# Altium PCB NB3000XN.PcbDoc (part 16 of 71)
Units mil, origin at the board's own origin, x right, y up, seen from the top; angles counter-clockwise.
Board outline 9527.56 x 6929.77 mil, 6 copper layers (Top Layer, GND+SHIELD, MidLayer1, MidLayer2, P2 - 3V3+5V0, Bottom Layer), stack 62.375 mil thick; 832 components, 1027 nets, 4655 pads, 4981 vias.
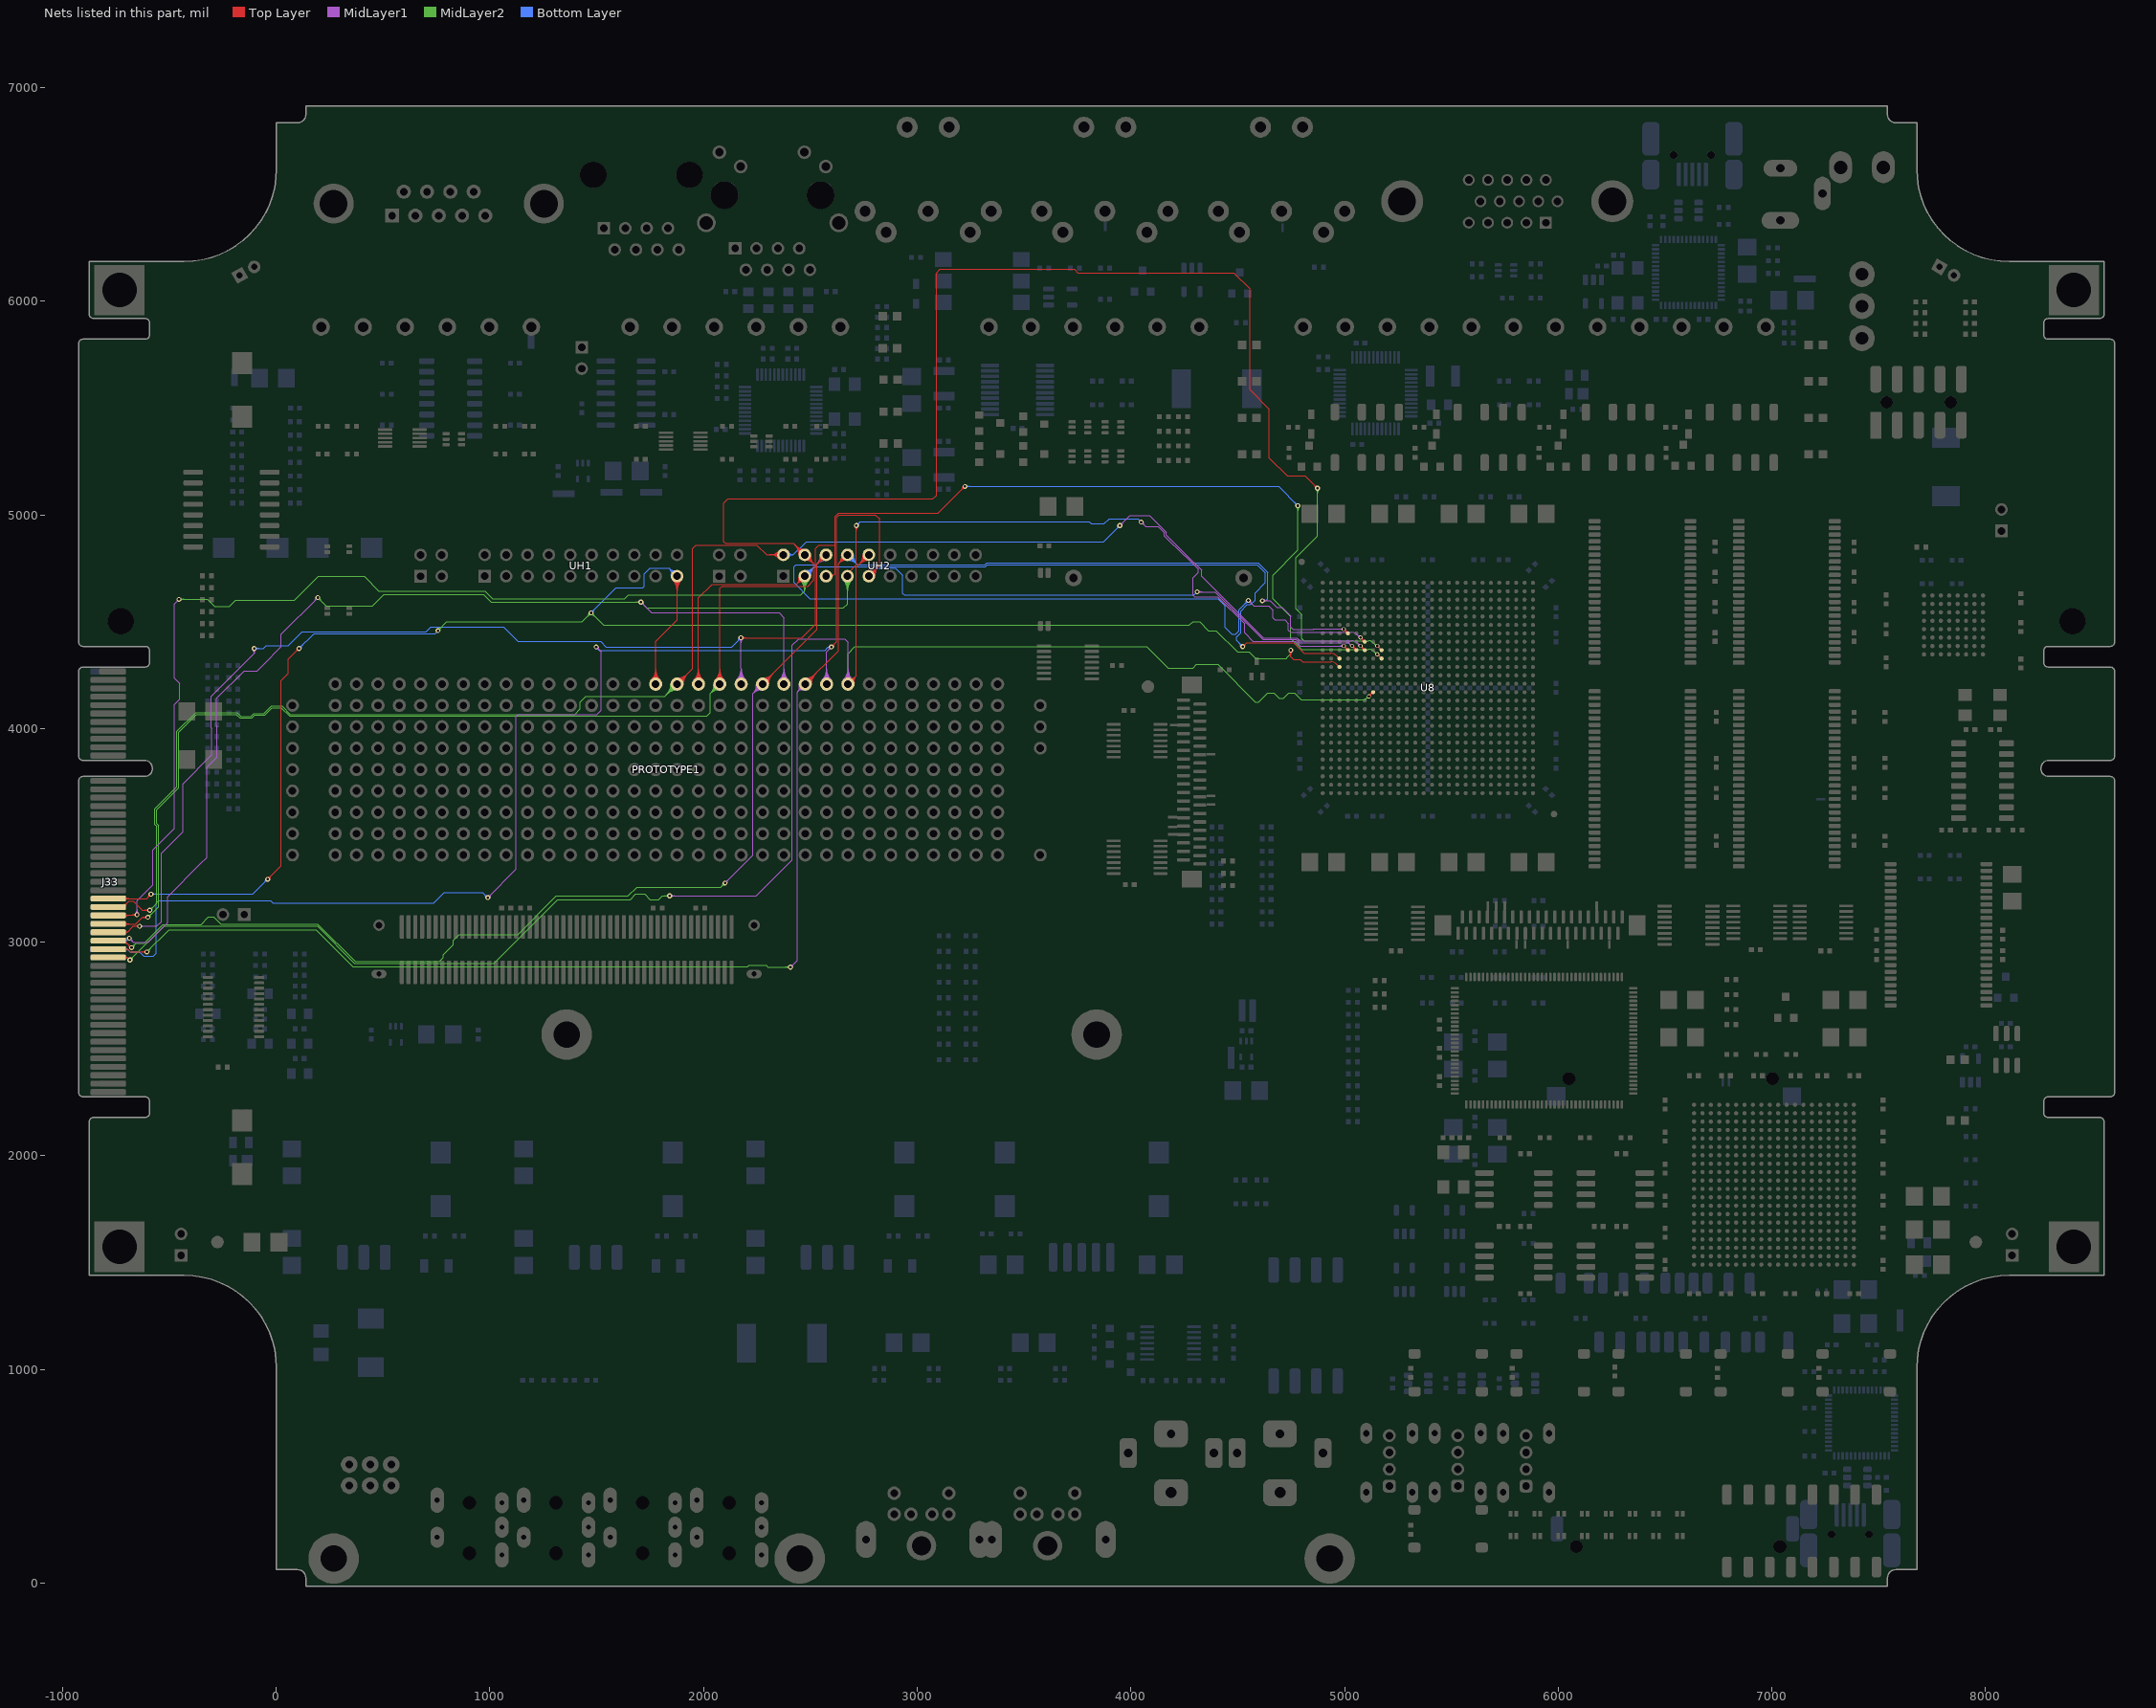
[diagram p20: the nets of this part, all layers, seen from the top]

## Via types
v1: diameter 23, hole 11.81, Top Layer to Bottom Layer, 3672 vias
v2: diameter 26, hole 11.81, Top Layer to Bottom Layer, 461 vias
v3: diameter 19, hole 11.81, Top Layer to Bottom Layer, tented both sides, 396 vias
v4: diameter 23.62, hole 11.81, Top Layer to Bottom Layer, 288 vias
v5: diameter 20, hole 11.81, Top Layer to Bottom Layer, 91 vias
v6: diameter 23, hole 11.81, Top Layer to Bottom Layer, tented both sides, 50 vias
v7: diameter 31, hole 11.81, Top Layer to Bottom Layer, 15 vias
v8: diameter 27.56, hole 11.81, Top Layer to Bottom Layer, tented both sides, 4 vias
v9: diameter 29, hole 11.81, Top Layer to Bottom Layer, 3 vias
v10: diameter 21, hole 11.81, Top Layer to Bottom Layer, 1 vias

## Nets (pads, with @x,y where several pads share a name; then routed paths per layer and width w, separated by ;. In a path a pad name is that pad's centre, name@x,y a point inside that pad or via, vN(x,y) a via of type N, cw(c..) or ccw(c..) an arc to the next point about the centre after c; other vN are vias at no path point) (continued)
ATE.UIO.IO17: J33.A26 PROTOTYPE1.H16 U8.L3 UH1.19 | length 9788.4
  Top Layer w4: J33.A26@-785.98,3204.04 -607.48,3204.04 v1(-586.48,3225.04) ; J33.A26@-711.58,3198.54 cw(c-698.3,3185.26) -698.3,3204.04 cw(c-698.3,3222.82) J33.A26@-711.58,3209.54 ; J33.A26@-708.76,3195.71 cw(c-688.65,3175.6) -688.65,3204.04 cw(c-688.65,3232.48) J33.A26@-708.76,3212.37 ; v1@-595.98,3225.04 cw(c-618.91,3225.04) -602.69,3208.82 cw(c-586.48,3192.61) v1@-586.48,3215.54 ; v1@-591.98,3225.04 cw(c-605.25,3225.04) -595.87,3215.65 cw(c-586.48,3206.26) v1@-586.48,3219.54 ; v1(-40,3295) 23.52,3358.52 23.52,4225.04 ; v1@-40,3300.5 ccw(c-40,3313.78) -30.61,3304.39 ccw(c-21.22,3295) v1@-34.5,3295 ; v1@-40,3304.5 ccw(c-40,3327.43) -23.78,3311.22 ccw(c-7.57,3295) v1@-30.5,3295 ; 43.96,4245.48 23.52,4225.04 ; v1@97.36,4375.04 cw(c74.42,4375.04) 90.64,4358.82 cw(c106.86,4342.61) v1@106.86,4365.54 ; v1@101.36,4375.04 cw(c88.08,4375.04) 97.47,4365.65 cw(c106.86,4356.26) v1@106.86,4369.54 ; v1(106.86,4375.04) 56.86,4325.04 56.86,4258.37 23.52,4225.04 ; PROTOTYPE1.H16@1755.62,4228.74 ccw(c1706.11,4278.25) 1776.12,4278.25 ccw(c1846.13,4278.25) PROTOTYPE1.H16@1796.63,4228.74 ; PROTOTYPE1.H16@1758.44,4225.91 ccw(c1715.77,4268.59) 1776.12,4268.59 ccw(c1836.48,4268.59) PROTOTYPE1.H16@1793.8,4225.91 ; PROTOTYPE1.H16@1761.27,4223.08 ccw(c1725.42,4258.93) 1776.12,4258.93 ccw(c1826.82,4258.93) PROTOTYPE1.H16@1790.97,4223.08 ; PROTOTYPE1.H16@1764.1,4220.26 ccw(c1735.08,4249.28) 1776.12,4249.28 ccw(c1817.16,4249.28) PROTOTYPE1.H16@1788.14,4220.26 ; PROTOTYPE1.H16@1766.93,4217.43 ccw(c1744.74,4239.62) 1776.12,4239.62 ccw(c1807.51,4239.62) PROTOTYPE1.H16@1785.31,4217.43 ; PROTOTYPE1.H16@1776.12,4208.23 1776.12,4408.37 1876.12,4508.37 UH1.19@1876.12,4713.23 ; UH1.19@1856.66,4693.77 cw(c1809.66,4646.78) 1876.12,4646.78 cw(c1942.58,4646.78) UH1.19@1895.59,4693.77 ; UH1.19@1859.48,4696.6 cw(c1819.32,4656.43) 1876.12,4656.43 cw(c1932.92,4656.43) UH1.19@1892.76,4696.6 ; UH1.19@1862.31,4699.43 cw(c1828.98,4666.09) 1876.12,4666.09 cw(c1923.26,4666.09) UH1.19@1889.93,4699.43 ; UH1.19@1865.14,4702.26 cw(c1838.63,4675.75) 1876.12,4675.75 cw(c1913.61,4675.75) UH1.19@1887.1,4702.26 ; v1@4741.81,4359.99 cw(c4725.59,4343.77) 4748.52,4343.77 cw(c4771.46,4343.77) v1@4755.24,4359.99 ; v1@4744.64,4362.82 cw(c4735.25,4353.43) 4748.52,4353.43 cw(c4761.8,4353.43) v1@4752.41,4362.82 ; v1@4755,4366.71 v1(4748.52,4366.71) 4748.52,4336.48 4761.6,4323.4 4792.92,4323.4 4804.03,4312.29 4809.42,4312.29 4823,4312.29 4855.26,4312.29 4860,4312.29 4870,4312.29 4936.73,4312.29 cw(c4936.73,4273.61) 4964.08,4300.96 ; U8.L3@4969.27,4288.43 ccw(c4951.55,4288.43) 4964.08,4300.96 ; U8.L3@4976.61,4295.77 cw(c4976.61,4313.49) 4964.08,4300.96
  MidLayer2 w4: v1(756.86,4458.37) 798.52,4500.04 1431.86,4500.04 v1(1473.52,4541.71) 1531.86,4483.37 4273.52,4483.37 4290.19,4500.04 4322.19,4500.04 4363.86,4458.37 4398.52,4458.37 4498.52,4358.37 4554.19,4358.37 4584.19,4328.37 4726.86,4328.37 4731.86,4333.37 4748.52,4350.04 ; v1@756.86,4463.87 ccw(c756.86,4477.15) 766.25,4467.76 ccw(c775.64,4458.37) v1@762.36,4458.37 ; v1@756.86,4467.87 ccw(c756.86,4490.81) 773.07,4474.59 ccw(c789.29,4458.37) v1@766.36,4458.37 ; v1@1464.02,4541.71 cw(c1441.09,4541.71) 1457.31,4525.49 cw(c1473.52,4509.27) 1473.52,4532.21 cw(c1473.52,4509.27) 1489.74,4525.49 cw(c1505.96,4541.71) v1@1483.02,4541.71 ; v1@1468.02,4541.71 cw(c1454.75,4541.71) 1464.14,4532.32 cw(c1473.52,4522.93) 1473.52,4536.21 cw(c1473.52,4522.93) 1482.91,4532.32 cw(c1492.3,4541.71) v1@1479.02,4541.71 ; v1@4743.68,4358.53 cw(c4738.65,4350.04) 4748.52,4350.04 ; v1(4748.52,4366.71) 4748.52,4350.04 ; v1@4753.36,4358.53 ccw(c4758.39,4350.04) 4748.52,4350.04
  Bottom Layer w4: v1(-586.48,3225.04) -109.96,3225.04 v1(-40,3295) ; v1@-582.59,3221.15 cw(c-573.2,3211.76) -573.2,3225.04 cw(c-573.2,3238.32) v1@-582.59,3228.93 ; v1@-579.76,3218.32 cw(c-563.54,3202.11) -563.54,3225.04 cw(c-563.54,3247.98) v1@-579.76,3231.76 ; v1@-49.5,3295 cw(c-72.44,3295) -56.22,3278.78 cw(c-40,3262.56) v1@-40,3285.5 ; v1@-45.5,3295 cw(c-58.78,3295) -49.39,3285.61 cw(c-40,3276.22) v1@-40,3289.5 ; v1(106.86,4375.04) 176.82,4445 743.48,4445 v1(756.86,4458.37) ; v1@106.86,4380.54 ccw(c106.86,4393.82) 116.25,4384.43 ccw(c125.64,4375.04) v1@112.36,4375.04 ; v1@106.86,4384.54 ccw(c106.86,4407.48) 123.07,4391.26 ccw(c139.29,4375.04) v1@116.36,4375.04 ; v1(1473.52,4541.71) 1590.19,4658.37 1715.19,4658.37 1723.52,4666.71 1723.52,4725.04 1748.52,4750.04 1831.86,4750.04 1839.32,4750.04 ; v1@1473.52,4547.21 ccw(c1473.52,4560.49) 1482.91,4551.1 ccw(c1492.3,4541.71) v1@1479.02,4541.71 ; v1@1473.52,4551.21 ccw(c1473.52,4574.14) 1489.74,4557.93 ccw(c1505.96,4541.71) v1@1483.02,4541.71 ; UH1.19@1849.08,4718.37 ccw(c1814.25,4724.98) 1839.32,4750.04 ; UH1.19@1853.01,4717.62 ccw(c1823.24,4723.27) 1844.66,4744.69 ccw(c1866.09,4766.11) UH1.19@1871.73,4736.35 ; UH1.19@1856.94,4716.88 ccw(c1832.23,4721.56) 1850.01,4739.34 ccw(c1867.79,4757.12) UH1.19@1872.48,4732.42 ; UH1.19@1870.99,4740.28 cw(c1864.38,4775.1) 1839.32,4750.04 ; UH1.19@1873.73,4715.62 1839.32,4750.04
ATE.UIO.IO18: J33.A27 PROTOTYPE1.H17 U8.J6 UH2.2 | length 9513.1
  Top Layer w4: J33.A27@-785.98,3164.67 -717.09,3164.67 -690.05,3191.71 -668.14,3191.71 -626.48,3150.04 v1(-591.81,3150.04) ; J33.A27@-717.08,3172.45 ccw(c-717.08,3191.23) -703.81,3177.95 ccw(c-690.52,3164.67) J33.A27@-709.3,3164.67 ; J33.A27@-717.08,3176.45 ccw(c-717.08,3204.89) -696.98,3184.78 ccw(c-676.86,3164.67) J33.A27@-705.3,3164.67 ; v1@-598.53,3143.32 ccw(c-614.74,3127.11) -614.74,3150.04 ccw(c-614.74,3172.98) v1@-598.53,3156.76 ; v1@-595.7,3146.15 ccw(c-605.09,3136.76) -605.09,3150.04 ccw(c-605.09,3163.32) v1@-595.7,3153.93 ; PROTOTYPE1.H17@1876.12,4208.23 1948.52,4280.64 1948.52,4841.71 1965.19,4858.37 2249.9,4858.37 2295.04,4813.23 UH2.2@2373.76,4813.23 ; PROTOTYPE1.H17@1876.12,4221.23 ccw(c1876.12,4252.62) 1898.31,4230.43 ccw(c1920.51,4208.23) PROTOTYPE1.H17@1889.12,4208.23 ; PROTOTYPE1.H17@1876.12,4225.23 ccw(c1876.12,4266.28) 1905.14,4237.26 ccw(c1934.16,4208.23) PROTOTYPE1.H17@1893.12,4208.23 ; PROTOTYPE1.H17@1876.12,4229.23 ccw(c1876.12,4279.93) 1911.97,4244.08 ccw(c1947.82,4208.23) PROTOTYPE1.H17@1897.12,4208.23 ; PROTOTYPE1.H17@1876.12,4233.23 ccw(c1876.12,4293.59) 1918.8,4250.91 ccw(c1961.48,4208.23) PROTOTYPE1.H17@1901.12,4208.23 ; PROTOTYPE1.H17@1876.12,4237.23 ccw(c1876.12,4307.25) 1925.63,4257.74 ccw(c1975.13,4208.23) PROTOTYPE1.H17@1905.12,4208.23 ; UH2.2@2354.29,4793.77 ccw(c2307.3,4746.78) 2307.3,4813.23 ccw(c2307.3,4879.69) UH2.2@2354.29,4832.7 ; UH2.2@2357.12,4796.6 ccw(c2316.96,4756.43) 2316.96,4813.23 ccw(c2316.96,4870.04) UH2.2@2357.12,4829.87 ; UH2.2@2359.95,4799.43 ccw(c2326.62,4766.09) 2326.62,4813.23 ccw(c2326.61,4860.38) UH2.2@2359.95,4827.04 ; UH2.2@2362.78,4802.25 ccw(c2336.27,4775.75) 2336.27,4813.23 ccw(c2336.27,4850.72) UH2.2@2362.78,4824.21 ; v3(5075.04,4386.85) U8.J6@5094.72,4367.17 ; U8.J6@5087.22,4367.17 ccw(c5069.12,4367.17) 5081.92,4379.97 ccw(c5094.72,4392.77) U8.J6@5094.72,4374.67 ; U8.J6@5087.38,4367.17 ccw(c5069.66,4367.17) 5082.19,4379.7 ccw(c5094.72,4392.23) U8.J6@5094.72,4374.51 ; 5087.84,4374.05 cw(c5100.65,4386.85) 5082.54,4386.85 ccw(c5100.65,4386.85) 5087.84,4374.05 ; 5087.84,4374.05 ccw(c5075.04,4361.24) 5075.04,4379.35 cw(c5075.04,4361.24) 5087.84,4374.05
  MidLayer1 w4: v1(3948.52,4950.04) 3990.19,4991.71 3996.29,4997.81 4087.38,4997.81 4165.69,4919.5 4165.69,4905.15 4254.29,4816.54 4256.42,4816.54 4331.86,4741.1 4331.86,4713.37 4620.19,4425.04 4776.24,4425.04 4790.56,4410.71 4815,4410.71 4860,4410.71 4870,4410.71 4918.62,4410.71 4938.04,4410.71 5012.16,4410.71 ; v1@3948.52,4955.54 ccw(c3948.52,4968.82) 3957.91,4959.43 ccw(c3967.3,4950.04) v1@3954.02,4950.04 ; v1@3948.52,4959.54 ccw(c3948.52,4982.48) 3964.74,4966.26 ccw(c3980.96,4950.04) v1@3958.02,4950.04 ; 4998.23,4410.71 5012.16,4410.71 ; v3@5067.57,4386.2 ccw(c5049.53,4384.62) 5061.17,4398.49 ; v3@5074.39,4394.32 cw(c5072.81,4412.36) 5061.17,4398.49 ; 5012.16,4410.71 5031.66,4410.71 cw(c5031.66,4368.98) 5061.17,4398.49
  MidLayer2 w4: v1(-591.81,3150.04) -559.81,3182.04 -559.81,3542.96 -568.31,3551.46 -568.31,3623.95 -465,3727.26 -465,3986.52 -376.48,4075.04 -183.81,4075.04 -167.14,4058.37 -166.27,4057.5 -117.35,4057.5 -104.35,4070.5 -57.02,4070.5 -22.52,4105 26.9,4105 65.19,4066.71 1398.52,4066.71 1423.52,4091.71 1423.52,4125.04 1448.52,4150.04 1817.93,4150.04 PROTOTYPE1.H17@1876.12,4208.23 ; v1@-591.81,3155.54 ccw(c-591.81,3168.82) -582.42,3159.43 ccw(c-573.03,3150.04) v1@-586.31,3150.04 ; v1@-591.81,3159.54 ccw(c-591.81,3182.48) -575.59,3166.26 ccw(c-559.37,3150.04) v1@-582.31,3150.04 ; PROTOTYPE1.H17@1847.12,4208.23 cw(c1777.11,4208.23) 1826.62,4158.73 cw(c1876.12,4109.22) PROTOTYPE1.H17@1876.12,4179.23 ; PROTOTYPE1.H17@1851.12,4208.23 cw(c1790.77,4208.23) 1833.44,4165.56 cw(c1876.12,4122.88) PROTOTYPE1.H17@1876.12,4183.23 ; PROTOTYPE1.H17@1855.12,4208.23 cw(c1804.42,4208.23) 1840.27,4172.39 cw(c1876.12,4136.54) PROTOTYPE1.H17@1876.12,4187.23 ; PROTOTYPE1.H17@1859.12,4208.23 cw(c1818.08,4208.23) 1847.1,4179.21 cw(c1876.12,4150.19) PROTOTYPE1.H17@1876.12,4191.23 ; PROTOTYPE1.H17@1863.12,4208.23 cw(c1831.74,4208.23) 1853.93,4186.04 cw(c1876.12,4163.85) PROTOTYPE1.H17@1876.12,4195.23
  Bottom Layer w4: UH2.2@2373.76,4813.23 2420.05,4813.23 2481.86,4875.04 3873.52,4875.04 v1(3948.52,4950.04) ; UH2.2@2390.92,4803.91 cw(c2406.6,4795.39) 2406.6,4813.23 cw(c2406.6,4831.08) UH2.2@2390.92,4822.56 ; UH2.2@2394.43,4802 cw(c2413.32,4791.73) 2413.32,4813.23 cw(c2413.32,4834.73) UH2.2@2394.43,4824.47 ; UH2.2@2397.95,4800.09 cw(c2420.05,4788.08) 2420.05,4813.23 cw(c2420.05,4838.39) UH2.2@2397.95,4826.38 ; v1@3939.02,4950.04 cw(c3916.09,4950.04) 3932.31,4933.82 cw(c3948.52,4917.61) v1@3948.52,4940.54 ; v1@3943.02,4950.04 cw(c3929.75,4950.04) 3939.14,4940.65 cw(c3948.52,4931.26) v1@3948.52,4944.54
ATE.UIO.IO19: J33.A28 PROTOTYPE1.H18 U8.K3 UH2.3 | length 10572.8
  Top Layer w4: J33.A28@-785.98,3125.3 -696.48,3125.3 ; J33.A28@-706.93,3119.32 cw(c-696.48,3113.16) -696.48,3125.3 ; J33.A28@-706.93,3131.28 ccw(c-696.48,3137.44) -696.48,3125.3 ; v1@-658.19,3121.66 ccw(c-674.41,3105.44) -674.41,3128.37 ccw(c-674.41,3151.31) v1@-658.19,3135.09 ; v1@-655.36,3124.49 ccw(c-664.75,3115.1) -664.75,3128.37 ccw(c-664.75,3141.65) v1@-655.36,3132.26 ; v1(-651.48,3128.37) -693.4,3128.37 -696.48,3125.3 ; PROTOTYPE1.H18@1955.62,4228.74 ccw(c1906.11,4278.25) 1976.12,4278.25 ccw(c2046.13,4278.25) PROTOTYPE1.H18@1996.63,4228.74 ; PROTOTYPE1.H18@1958.44,4225.91 ccw(c1915.77,4268.59) 1976.12,4268.59 ccw(c2036.48,4268.59) PROTOTYPE1.H18@1993.8,4225.91 ; PROTOTYPE1.H18@1961.27,4223.08 ccw(c1925.42,4258.93) 1976.12,4258.93 ccw(c2026.82,4258.93) PROTOTYPE1.H18@1990.97,4223.08 ; PROTOTYPE1.H18@1964.1,4220.26 ccw(c1935.08,4249.28) 1976.12,4249.28 ccw(c2017.16,4249.28) PROTOTYPE1.H18@1988.14,4220.26 ; PROTOTYPE1.H18@1966.93,4217.43 ccw(c1944.74,4239.62) 1976.12,4239.62 ccw(c2007.51,4239.62) PROTOTYPE1.H18@1985.31,4217.43 ; PROTOTYPE1.H18@1976.12,4208.23 1976.12,4611.12 2040.04,4675.04 2435.57,4675.04 ; UH2.3@2446.57,4708.92 cw(c2407.83,4702.78) 2435.57,4675.04 ; UH2.3@2450.52,4709.55 cw(c2417.41,4704.3) 2441.12,4680.59 cw(c2464.82,4656.89) UH2.3@2470.07,4690 ; UH2.3@2454.47,4710.17 cw(c2426.99,4705.82) 2446.67,4686.14 cw(c2466.34,4666.47) UH2.3@2470.7,4693.95 ; UH2.3@2458.42,4710.8 cw(c2436.57,4707.33) 2452.22,4691.69 cw(c2467.86,4676.05) UH2.3@2471.33,4697.9 ; UH2.3@2469.45,4686.05 ccw(c2463.3,4647.31) 2435.57,4675.04 ; UH2.3@2473.76,4713.23 2435.57,4675.04 ; v1(4523.52,4383.71) 4541.69,4401.87 4738,4401.87 4760.76,4401.87 4810.97,4351.66 4815.97,4351.66 4824,4351.66 4860,4351.66 ; v1@4523.52,4389.21 ccw(c4523.52,4402.49) 4532.91,4393.1 ccw(c4542.3,4383.71) v1@4529.02,4383.71 ; v1@4523.52,4393.21 ccw(c4523.52,4416.14) 4539.74,4399.93 ccw(c4555.96,4383.71) v1@4533.02,4383.71 ; 4856.86,4351.66 4855.26,4351.66 4860,4351.66 ; 4860,4351.66 4870,4351.66 4873.88,4351.66 4936.73,4351.66 ; 4936.73,4351.66 cw(c4936.73,4312.98) 4964.08,4340.33 ; 4936.73,4351.66 cw(c4936.73,4312.98) 4964.08,4340.33 ; 4964.08,4340.33 cw(c4951.55,4327.8) 4969.27,4327.8 ccw(c4951.55,4327.8) 4964.08,4340.33 ; 4964.08,4340.33 ccw(c4976.61,4352.86) 4976.61,4335.14 cw(c4976.61,4352.86) 4964.08,4340.33
  MidLayer1 w4: v1@-658.19,3135.09 ccw(c-674.41,3151.31) -651.48,3151.31 ccw(c-628.54,3151.31) v1@-644.76,3135.09 ; v1@-655.36,3132.26 ccw(c-664.75,3141.65) -651.48,3141.65 ccw(c-638.2,3141.65) v1@-647.59,3132.26 ; v1(-651.48,3128.37) -651.48,3195 -577,3269.48 -577,3432.85 -476.81,3533.04 -476.81,4113.26 -452,4138.06 -452,4211.93 -476.81,4236.74 -476.81,4583.19 v1(-455,4605)
  MidLayer2 w4: v1(-455,4605) -322.72,4605 -288.6,4570.87 -219.43,4570.87 -188.93,4601.37 86.63,4601.37 162.03,4676.78 197.25,4712 411.56,4712 479.75,4643.81 977.38,4643.81 1013.48,4607.71 1631.39,4607.71 1648.39,4624.71 2454.71,4624.71 2473.76,4643.76 UH2.3@2473.76,4713.23 ; v1@-451.11,4601.11 cw(c-441.72,4591.72) -441.72,4605 cw(c-441.72,4618.28) v1@-451.11,4608.89 ; v1@-448.28,4598.28 cw(c-432.07,4582.06) -432.07,4605 cw(c-432.07,4627.93) v1@-448.28,4611.72 ; UH2.3@2454.29,4693.77 cw(c2407.3,4646.78) 2473.76,4646.78 cw(c2540.22,4646.78) UH2.3@2493.22,4693.77 ; UH2.3@2457.12,4696.6 cw(c2416.96,4656.43) 2473.76,4656.43 cw(c2530.56,4656.43) UH2.3@2490.4,4696.6 ; UH2.3@2459.95,4699.43 cw(c2426.62,4666.09) 2473.76,4666.09 cw(c2520.9,4666.09) UH2.3@2487.57,4699.43 ; UH2.3@2462.78,4702.25 cw(c2436.27,4675.75) 2473.76,4675.75 cw(c2511.25,4675.75) UH2.3@2484.74,4702.25
  Bottom Layer w4: UH2.3@2474.21,4728.76 ccw(c2475.19,4762.73) 2499.22,4738.7 ccw(c2523.25,4714.66) UH2.3@2489.28,4713.68 ; UH2.3@2474.32,4732.75 ccw(c2475.56,4775.48) 2505.78,4745.25 ccw(c2536,4715.03) UH2.3@2493.28,4713.8 ; UH2.3@2474.44,4736.75 ccw(c2475.92,4788.23) 2512.34,4751.81 ccw(c2548.75,4715.4) UH2.3@2497.28,4713.91 ; UH2.3@2474.55,4740.75 ccw(c2476.29,4800.98) 2518.9,4758.37 ccw(c2561.5,4715.77) UH2.3@2501.27,4714.03 ; v1@4514.02,4383.71 ccw(c4491.09,4383.71) 4507.31,4399.93 ccw(c4523.52,4416.14) v1@4523.52,4393.21 ; v1@4518.02,4383.71 ccw(c4504.75,4383.71) 4514.14,4393.1 ccw(c4523.52,4402.49) v1@4523.52,4389.21 ; v1(4523.52,4383.71) 4495,4412.23 4495,4429.6 4514.86,4449.46 4514.86,4550 4544.86,4580 4560,4580 4581.86,4601.86 4581.86,4635 4630,4683.14 4630,4729.27 4591.56,4767.71 3329.02,4767.71 3319.69,4758.37 2518.9,4758.37 UH2.3@2490.19,4729.67 ; UH2.3@2490.19,4729.67 2490.19,4713.23 UH2.3@2473.76,4713.23 UH2.3@2490.19,4729.67
ATE.UIO.IO20: J33.A29 PROTOTYPE1.H19 U8.J8 UH2.4 | length 13015.3
  Top Layer w4: J33.A29@-785.98,3085.93 -657.25,3085.93 -626.48,3116.71 v1(-600.48,3116.71) ; J33.A29@-711.58,3080.43 cw(c-698.3,3067.15) -698.3,3085.93 cw(c-698.3,3104.71) J33.A29@-711.58,3091.43 ; J33.A29@-708.76,3077.6 cw(c-688.65,3057.49) -688.65,3085.93 cw(c-688.65,3114.37) J33.A29@-708.76,3094.26 ; v1@-607.19,3109.99 ccw(c-623.41,3093.77) -623.41,3116.71 ccw(c-623.41,3139.64) v1@-607.19,3123.43 ; v1@-604.36,3112.82 ccw(c-613.75,3103.43) -613.75,3116.71 ccw(c-613.75,3129.99) v1@-604.36,3120.6 ; PROTOTYPE1.H19@2055.62,4228.74 ccw(c2006.11,4278.25) 2076.12,4278.25 ccw(c2146.13,4278.25) PROTOTYPE1.H19@2096.63,4228.74 ; PROTOTYPE1.H19@2058.44,4225.91 ccw(c2015.77,4268.59) 2076.12,4268.59 ccw(c2136.48,4268.59) PROTOTYPE1.H19@2093.8,4225.91 ; PROTOTYPE1.H19@2061.27,4223.08 ccw(c2025.42,4258.93) 2076.12,4258.93 ccw(c2126.82,4258.93) PROTOTYPE1.H19@2090.97,4223.08 ; PROTOTYPE1.H19@2064.1,4220.26 ccw(c2035.08,4249.28) 2076.12,4249.28 ccw(c2117.16,4249.28) PROTOTYPE1.H19@2088.14,4220.26 ; PROTOTYPE1.H19@2066.93,4217.43 ccw(c2044.74,4239.62) 2076.12,4239.62 ccw(c2107.51,4239.62) PROTOTYPE1.H19@2085.31,4217.43 ; PROTOTYPE1.H19@2076.12,4208.23 2076.12,4656.12 2086.71,4666.71 2487.86,4666.71 2515.19,4694.04 2515.19,4771.8 ; UH2.4@2446.23,4813.23 ccw(c2379.77,4813.23) 2426.77,4860.23 ccw(c2473.76,4907.22) UH2.4@2473.76,4840.76 ; UH2.4@2450.23,4813.23 ccw(c2393.43,4813.23) 2433.59,4853.4 ccw(c2473.76,4893.56) UH2.4@2473.76,4836.76 ; UH2.4@2454.23,4813.23 ccw(c2407.09,4813.23) 2440.42,4846.57 ccw(c2473.76,4879.91) UH2.4@2473.76,4832.76 ; UH2.4@2458.23,4813.23 ccw(c2420.74,4813.23) 2447.25,4839.74 ccw(c2473.76,4866.25) UH2.4@2473.76,4828.76 ; UH2.4@2475.2,4797.77 cw(c2477.75,4770.48) 2497.13,4789.86 cw(c2516.51,4809.25) UH2.4@2489.22,4811.79 ; UH2.4@2475.57,4793.79 cw(c2478.78,4759.47) 2503.15,4783.84 cw(c2527.52,4808.22) UH2.4@2493.2,4811.42 ; UH2.4@2475.94,4789.81 cw(c2479.8,4748.46) 2509.17,4777.82 cw(c2538.53,4807.19) UH2.4@2497.18,4811.05 ; UH2.4@2476.32,4785.83 cw(c2480.83,4737.45) 2515.19,4771.8 ; UH2.4@2501.17,4810.68 ccw(c2549.55,4806.16) 2515.19,4771.8 ; v1@4864.02,5125.04 ccw(c4841.09,5125.04) 4857.31,5141.26 ccw(c4873.52,5157.48) v1@4873.52,5134.54 ; v1@4868.02,5125.04 ccw(c4854.75,5125.04) 4864.14,5134.43 ccw(c4873.52,5143.82) v1@4873.52,5130.54 ; v1(4873.52,5125.04) 4815.19,5183.37 4731.86,5183.37 4648.19,5267.04 4648.19,5495.02 4556.86,5586.36 4556.86,6058.37 4481.86,6133.37 3751.67,6133.37 3735,6150.04 3106.86,6150.04 3090.19,6133.37 3090.19,5091.71 3073.48,5075 2115,5075 2095,5055 2095,4875 2103.29,4866.71 2420.29,4866.71 UH2.4@2473.41,4813.58 ; v3(5153.78,4386.85) U8.J8@5173.46,4367.17 ; U8.J8@5165.96,4367.17 ccw(c5147.86,4367.17) 5160.66,4379.97 ccw(c5173.46,4392.77) U8.J8@5173.46,4374.67 ; U8.J8@5166.12,4367.17 ccw(c5148.4,4367.17) 5160.93,4379.7 ccw(c5173.46,4392.23) U8.J8@5173.46,4374.51 ; UH2.4@2473.41,4813.58 UH2.4@2473.76,4813.23 ; UH2.4@2473.41,4813.58 UH2.4@2473.76,4813.23 ; UH2.4@2473.76,4813.23 2515.19,4771.8 ; 5166.58,4374.05 cw(c5179.39,4386.85) 5161.28,4386.85 ccw(c5179.39,4386.85) 5166.58,4374.05 ; 5166.58,4374.05 ccw(c5153.78,4361.24) 5153.78,4379.35 cw(c5153.78,4361.24) 5166.58,4374.05
  MidLayer2 w4: v1@-600.48,3122.21 ccw(c-600.48,3137.09) -589.95,3126.57 ; v1@-600.48,3126.21 ccw(c-600.48,3150.75) -583.12,3133.4 ; v1@-599.81,3116.71 -551.48,3165.04 -551.48,3545.94 -560.31,3554.78 -560.31,3620.64 -457,3723.95 -457,3983.2 -373.5,4066.71 -186.79,4066.71 -169.58,4049.5 -114.04,4049.5 -101.04,4062.5 -96.35,4062.5 -95,4062.5 -53.7,4062.5 -19.2,4097 23.58,4097 62.21,4058.37 2015.19,4058.37 2031.86,4075.04 2031.86,4163.97 ; v1@-594.98,3116.71 cw(c-583.31,3116.71) -591.56,3124.96 ; v1@-590.98,3116.71 cw(c-569.65,3116.71) -584.73,3131.79 ; PROTOTYPE1.H19@2047.22,4205.85 cw(c1994.34,4201.49) 2031.86,4163.97 ; PROTOTYPE1.H19@2051.21,4206.18 cw(c2005.62,4202.42) 2037.96,4170.08 cw(c2070.31,4137.74) PROTOTYPE1.H19@2074.07,4183.32 ; PROTOTYPE1.H19@2055.19,4206.51 cw(c2016.9,4203.35) 2044.07,4176.18 cw(c2071.24,4149.02) PROTOTYPE1.H19@2074.39,4187.31 ; PROTOTYPE1.H19@2059.18,4206.84 cw(c2028.18,4204.28) 2050.17,4182.29 cw(c2072.17,4160.3) PROTOTYPE1.H19@2074.72,4191.29 ; PROTOTYPE1.H19@2073.74,4179.33 ccw(c2069.37,4126.46) 2031.86,4163.97 ; PROTOTYPE1.H19@2076.12,4208.23 2031.86,4163.97 ; v1@4866.81,5118.32 cw(c4850.59,5102.11) 4873.52,5102.11 cw(c4896.46,5102.11) v1@4880.24,5118.32 ; v1@4869.64,5121.15 cw(c4860.25,5111.76) 4873.52,5111.76 cw(c4886.8,5111.76) v1@4877.41,5121.15 ; v1(4873.52,5125.04) 4873.52,4900.04 4773.52,4800.04 4773.52,4559.69 4800,4533.21 4800,4421.31 4810.6,4410.71 4860,4410.71 4870,4410.71 4997.36,4410.71 5016.78,4410.71 5090.9,4410.71 5114.15,4410.71 cw(c5114.15,4386.94) 5130.37,4404.32 5138.95,4397.24 ; v3@5146.39,4385.55 ccw(c5128.56,4382.4) 5138.95,4397.24 ; v3@5152.48,4394.24 cw(c5149.33,4412.07) 5138.95,4397.24
ATE.UIO.IO21: J33.A30 PROTOTYPE1.H20 U8.K8 UH2.5 | length 10026.4
  Top Layer w4: J33.A30@-785.98,3046.56 -696.62,3046.56 ; J33.A30@-706.9,3040.65 cw(c-696.62,3034.68) -696.62,3046.56 ; J33.A30@-706.9,3052.48 ccw(c-696.62,3058.44) -696.62,3046.56 ; v1@-646.19,3068.32 ccw(c-662.41,3052.11) -662.41,3075.04 ccw(c-662.41,3097.98) v1@-646.19,3081.76 ; v1@-643.36,3071.15 ccw(c-652.75,3061.76) -652.75,3075.04 ccw(c-652.75,3088.32) v1@-643.36,3078.93 ; v1(-639.48,3075.04) -668.14,3075.04 -696.62,3046.56 ; v1(2175,4425.04) 2460.04,4425.04 2523.52,4488.52 2523.52,4841.71 2540.19,4858.37 2615.19,4858.37 ; v1@2178.89,4421.15 cw(c2188.28,4411.76) 2188.28,4425.04 cw(c2188.28,4438.32) v1@2178.89,4428.93 ; v1@2181.72,4418.32 cw(c2197.93,4402.11) 2197.93,4425.04 cw(c2197.93,4447.98) v1@2181.72,4431.76 ; UH2.5@2573.76,4713.23 2573.76,4716.71 2606.86,4716.71 ; UH2.5@2599.94,4721.73 ccw(c2606.86,4723.98) 2606.86,4716.71 ; UH2.5@2601.23,4711.44 cw(c2606.86,4711.07) 2606.86,4716.71 ; v1@3214.02,5133.37 cw(c3191.09,5133.37) 3207.31,5117.16 cw(c3223.52,5100.94) v1@3223.52,5123.87 ; v1@3218.02,5133.37 cw(c3204.75,5133.37) 3214.14,5123.99 cw(c3223.52,5114.6) v1@3223.52,5127.87 ; v1(3223.52,5133.37) 3098.52,5008.37 2631.86,5008.37 2615.19,4991.71 2615.19,4858.37 ; v3(5153.78,4347.48) U8.K8@5173.46,4327.8 ; U8.K8@5165.96,4327.8 ccw(c5147.86,4327.8) 5160.66,4340.6 ccw(c5173.46,4353.4) U8.K8@5173.46,4335.3 ; U8.K8@5166.12,4327.8 ccw(c5148.4,4327.8) 5160.93,4340.33 ccw(c5173.46,4352.86) U8.K8@5173.46,4335.14 ; 2606.86,4716.71 2615.19,4725.04 2615.19,4858.37 ; 5166.58,4334.68 cw(c5179.39,4347.48) 5161.28,4347.48 ccw(c5179.39,4347.48) 5166.58,4334.68 ; 5166.58,4334.68 ccw(c5153.78,4321.87) 5153.78,4339.98 cw(c5153.78,4321.87) 5166.58,4334.68
  MidLayer1 w4: v1(-639.48,3075.04) -558.65,3075.04 -537,3096.69 -537,3204.51 -536.98,3416.31 -436.81,3516.47 -436.81,3741.13 -301.23,3876.71 -301.23,4000.15 -303,4001.92 -303,4151.5 -102.81,4351.69 v1(-102.81,4375.04) ; v1@-109.53,4368.32 cw(c-125.74,4352.11) -102.81,4352.11 cw(c-79.87,4352.11) v1@-96.09,4368.32 ; v1@-106.7,4371.15 cw(c-116.09,4361.76) -102.81,4361.76 cw(c-89.53,4361.76) v1@-98.92,4371.15 ; PROTOTYPE1.H20@2155.62,4228.74 ccw(c2106.11,4278.25) 2176.12,4278.25 ccw(c2246.13,4278.25) PROTOTYPE1.H20@2196.63,4228.74 ; PROTOTYPE1.H20@2158.44,4225.91 ccw(c2115.77,4268.59) 2176.12,4268.59 ccw(c2236.48,4268.59) PROTOTYPE1.H20@2193.8,4225.91 ; PROTOTYPE1.H20@2161.27,4223.08 ccw(c2125.42,4258.93) 2176.12,4258.93 ccw(c2226.82,4258.93) PROTOTYPE1.H20@2190.97,4223.08 ; PROTOTYPE1.H20@2164.1,4220.26 ccw(c2135.08,4249.28) 2176.12,4249.28 ccw(c2217.16,4249.28) PROTOTYPE1.H20@2188.14,4220.26 ; PROTOTYPE1.H20@2166.93,4217.43 ccw(c2144.74,4239.62) 2176.12,4239.62 ccw(c2207.51,4239.62) PROTOTYPE1.H20@2185.31,4217.43 ; v1@2168.28,4418.32 cw(c2152.06,4402.11) 2175,4402.11 cw(c2197.93,4402.11) v1@2181.72,4418.32 ; v1@2171.11,4421.15 cw(c2161.72,4411.76) 2175,4411.76 cw(c2188.28,4411.76) v1@2178.89,4421.15 ; v1(2175,4425.04) 2175,4281.12 2176.12,4280 PROTOTYPE1.H20@2176.12,4208.23
  MidLayer2 w4: v1@4775.14,5036.32 cw(c4758.92,5020.11) 4781.86,5020.11 cw(c4804.79,5020.11) v1@4788.57,5036.32 ; v1@4777.97,5039.15 cw(c4768.58,5029.76) 4781.86,5029.76 cw(c4795.14,5029.76) v1@4785.75,5039.15 ; v1(4781.86,5043.04) 4781.86,4835.75 4664.19,4718.08 4664.19,4608.37 4748.52,4524.04 4748.52,4422.67 4799.85,4371.34 4840,4371.34 4860,4371.34 4870,4371.34 4997.36,4371.34 5016.78,4371.34 5090.9,4371.34 5110.4,4371.34 cw(c5110.4,4329.61) 5139.91,4359.12 ; v3@5146.31,4346.83 ccw(c5128.27,4345.25) 5139.91,4359.12 ; v3@5153.13,4354.95 cw(c5151.55,4372.99) 5139.91,4359.12
  Bottom Layer w4: v1(-102.81,4375.04) -60,4375.04 -46.04,4389 56.63,4389 80.34,4412.72 120.63,4453 700.63,4453 724.19,4476.56 1063.67,4476.56 1089.76,4450.48 1115.19,4425.04 1132.19,4408.04 1518.31,4408.04 1543.98,4382.37 2132.33,4382.37 v1(2175,4425.04) ; v1@-98.92,4371.15 cw(c-89.53,4361.76) -89.53,4375.04 cw(c-89.53,4388.32) v1@-98.92,4378.93 ; v1@-96.09,4368.32 cw(c-79.87,4352.11) -79.87,4375.04 cw(c-79.87,4397.98) v1@-96.09,4381.76 ; v1@2165.5,4425.04 cw(c2142.56,4425.04) 2158.78,4408.82 cw(c2175,4392.61) v1@2175,4415.54 ; v1@2169.5,4425.04 cw(c2156.22,4425.04) 2165.61,4415.65 cw(c2175,4406.26) v1@2175,4419.54 ; v1(3223.52,5133.37) 4691.52,5133.37 v1(4781.86,5043.04) ; v1@3227.41,5129.49 cw(c3236.8,5120.1) 3236.8,5133.37 cw(c3236.8,5146.65) v1@3227.41,5137.26 ; v1@3230.24,5126.66 cw(c3246.46,5110.44) 3246.46,5133.37 cw(c3246.46,5156.31) v1@3230.24,5140.09 ; v1@4772.36,5043.04 ccw(c4749.42,5043.04) 4765.64,5059.26 ccw(c4781.86,5075.48) v1@4781.86,5052.54 ; v1@4776.36,5043.04 ccw(c4763.08,5043.04) 4772.47,5052.43 ccw(c4781.86,5061.82) v1@4781.86,5048.54
ATE.UIO.IO22: J33.A31 PROTOTYPE1.H21 U8.H6 UH2.6 | length 10136.4
  Top Layer w4: J33.A31@-785.98,3007.19 -770,3007.19 -767.19,3010 -712.77,3010 v1(-677.14,2974.37) ; J33.A31@-717.08,2995.41 cw(c-717.08,2949.77) v1@-684.81,2982.05 ; J33.A31@-717.08,2999.41 cw(c-717.08,2963.43) -691.64,2988.87 ; J33.A31@-717.08,3003.41 cw(c-717.08,2977.09) -698.47,2995.7 ; J33.A31@-705.3,3007.19 ccw(c-694.07,3007.19) -702.01,2999.25 ; v1@-686.64,2974.37 ccw(c-709.58,2974.37) -693.36,2990.59 ccw(c-677.14,3006.81) v1@-677.14,2983.87 ; v1@-682.64,2974.37 ccw(c-695.92,2974.37) -686.53,2983.76 ccw(c-677.14,2993.15) v1@-677.14,2979.87 ; PROTOTYPE1.H21@2276.12,4208.23 2531.86,4463.97 2531.86,4771.33 ; PROTOTYPE1.H21@2276.12,4221.23 ccw(c2276.12,4252.62) 2298.31,4230.43 ccw(c2320.51,4208.23) PROTOTYPE1.H21@2289.12,4208.23 ; PROTOTYPE1.H21@2276.12,4225.23 ccw(c2276.12,4266.28) 2305.14,4237.26 ccw(c2334.16,4208.23) PROTOTYPE1.H21@2293.12,4208.23 ; PROTOTYPE1.H21@2276.12,4229.23 ccw(c2276.12,4279.93) 2311.97,4244.08 ccw(c2347.82,4208.23) PROTOTYPE1.H21@2297.12,4208.23 ; PROTOTYPE1.H21@2276.12,4233.23 ccw(c2276.12,4293.59) 2318.8,4250.91 ccw(c2361.48,4208.23) PROTOTYPE1.H21@2301.12,4208.23 ; PROTOTYPE1.H21@2276.12,4237.23 ccw(c2276.12,4307.25) 2325.63,4257.74 ccw(c2375.13,4208.23) PROTOTYPE1.H21@2305.12,4208.23 ; UH2.6@2546.33,4810.91 cw(c2496.5,4806.7) 2531.86,4771.33 ; UH2.6@2550.31,4811.25 cw(c2507.72,4807.65) 2537.95,4777.42 cw(c2568.17,4747.2) UH2.6@2571.78,4789.79 ; UH2.6@2554.3,4811.59 cw(c2518.95,4808.6) 2544.04,4783.51 cw(c2569.12,4758.42) UH2.6@2572.11,4793.78 ; UH2.6@2558.29,4811.93 cw(c2530.18,4809.55) 2550.12,4789.6 cw(c2570.07,4769.65) UH2.6@2572.45,4797.76 ; UH2.6@2571.44,4785.8 ccw(c2567.22,4735.97) 2531.86,4771.33 ; UH2.6@2573.76,4813.23 2531.86,4771.33 ; v3(5075.04,4426.22) U8.H6@5094.72,4406.54 ; U8.H6@5087.22,4406.54 ccw(c5069.12,4406.54) 5081.92,4419.34 ccw(c5094.72,4432.14) U8.H6@5094.72,4414.04 ; U8.H6@5087.38,4406.54 ccw(c5069.66,4406.54) 5082.19,4419.07 ccw(c5094.72,4431.6) U8.H6@5094.72,4413.88 ; 5087.84,4413.42 cw(c5100.65,4426.22) 5082.54,4426.22 ccw(c5100.65,4426.22) 5087.84,4413.42 ; 5087.84,4413.42 ccw(c5075.04,4400.61) 5075.04,4418.72 cw(c5075.04,4400.61) 5087.84,4413.42
  MidLayer1 w4: v1(2100.52,3277.04) 2231.86,3408.37 2231.86,4163.97 ; v1@2100.52,3282.54 ccw(c2100.52,3295.82) 2109.91,3286.43 ccw(c2119.3,3277.04) v1@2106.02,3277.04 ; v1@2100.52,3286.54 ccw(c2100.52,3309.48) 2116.74,3293.26 ccw(c2132.96,3277.04) v1@2110.02,3277.04 ; PROTOTYPE1.H21@2247.22,4205.85 cw(c2194.34,4201.49) 2231.86,4163.97 ; PROTOTYPE1.H21@2251.21,4206.18 cw(c2205.62,4202.42) 2237.96,4170.08 cw(c2270.31,4137.74) PROTOTYPE1.H21@2274.07,4183.32 ; PROTOTYPE1.H21@2255.19,4206.51 cw(c2216.9,4203.35) 2244.07,4176.18 cw(c2271.24,4149.02) PROTOTYPE1.H21@2274.39,4187.31 ; PROTOTYPE1.H21@2259.18,4206.84 cw(c2228.18,4204.28) 2250.17,4182.29 cw(c2272.17,4160.3) PROTOTYPE1.H21@2274.72,4191.29 ; PROTOTYPE1.H21@2273.74,4179.33 ccw(c2269.37,4126.46) 2231.86,4163.97 ; PROTOTYPE1.H21@2276.12,4208.23 2231.86,4163.97 ; v1@4546.86,4601.71 v1@4549.28,4599.28 ; v1@4550,4590.5 cw(c4550,4567.56) 4566.22,4583.78 cw(c4582.43,4600) v1@4559.5,4600 ; v1@4550,4594.5 cw(c4550,4581.22) 4559.39,4590.61 cw(c4568.78,4600) v1@4555.5,4600 ; v1(4550,4600) 4575,4575 4645,4575 4665,4555 4665,4518.37 4675,4508.37 4721.19,4508.37 4737.86,4491.71 4737.86,4459.71 4747.48,4450.08 4855.26,4450.08 4860,4450.08 4870,4450.08 4918.62,4450.08 4938.04,4450.08 5012.16,4450.08 ; 4998.23,4450.08 5012.16,4450.08 ; v3@5067.57,4425.57 ccw(c5049.53,4423.99) 5061.17,4437.86 ; v3@5074.39,4433.69 cw(c5072.81,4451.73) 5061.17,4437.86 ; 5012.16,4450.08 5031.66,4450.08 cw(c5031.66,4408.35) 5061.17,4437.86
  MidLayer2 w4: v1(-677.14,2974.37) -656.36,2995.16 -617.67,2995.16 -529.79,3083.04 -351.96,3083.04 -316.67,3118.33 -293.33,3118.33 -260,3085 193.94,3085 368.94,2910 765,2910 782.36,2927.36 782.36,2941.46 829.82,2988.93 829.82,3009.82 855,3035 1130.5,3035 1311.54,3216.04 1646.04,3216.04 1688.37,3258.37 2081.86,3258.37 v1(2100.52,3277.04) ; v1@-677.14,2979.87 ccw(c-677.14,2993.15) -667.75,2983.76 ccw(c-658.36,2974.37) v1@-671.64,2974.37 ; v1@-677.14,2983.87 ccw(c-677.14,3006.81) -660.93,2990.59 ccw(c-644.71,2974.37) v1@-667.64,2974.37 ; v1@2091.02,3277.04 cw(c2068.09,3277.04) 2084.31,3260.82 cw(c2100.52,3244.61) v1@2100.52,3267.54 ; v1@2095.02,3277.04 cw(c2081.75,3277.04) 2091.13,3267.65 cw(c2100.52,3258.26) v1@2100.52,3271.54
  Bottom Layer w4: 2431.37,4765 2430,4765 2423.19,4758.19 2423.19,4683.12 2497.94,4608.37 4406.86,4608.37 4440.19,4575.04 4440.19,4473.71 4472.19,4441.71 4490.19,4441.71 4506.86,4458.37 4506.86,4556.86 v1(4550,4600) ; 2431.37,4766.37 2526.9,4766.37 ; UH2.6@2546.23,4813.18 cw(c2480.24,4813.04) 2526.9,4766.38 ; UH2.6@2550.23,4813.19 cw(c2493.83,4813.07) 2533.71,4773.19 cw(c2573.6,4733.3) UH2.6@2573.71,4789.71 ; UH2.6@2554.23,4813.19 cw(c2507.42,4813.1) 2540.52,4779.99 cw(c2573.62,4746.89) UH2.6@2573.72,4793.71 ; UH2.6@2558.23,4813.2 cw(c2521.01,4813.13) 2547.33,4786.8 cw(c2573.65,4760.48) UH2.6@2573.73,4797.71 ; UH2.6@2573.7,4785.71 ccw(c2573.57,4719.71) 2526.9,4766.38 ; UH2.6@2573.76,4813.23 2526.9,4766.37 ; v1@4540.5,4600 cw(c4517.56,4600) 4533.78,4583.78 cw(c4550,4567.56) v1@4550,4590.5 ; v1@4544.5,4600 cw(c4531.22,4600) 4540.61,4590.61 cw(c4550,4581.22) v1@4550,4594.5
ATE.UIO.IO23: J33.B31 PROTOTYPE1.H22 U8.J4 UH2.7 | length 10243.9
  Top Layer w4: UH2.7@2673.76,4713.23 2673.76,4716.71 2673.52,4716.71 2673.52,4725.04 2715.19,4766.71 v1(2715.19,4950.04) ; v1@2708.47,4943.32 cw(c2692.26,4927.11) 2715.19,4927.11 cw(c2738.13,4927.11) v1@2721.91,4943.32 ; v1@2711.3,4946.15 cw(c2701.91,4936.76) 2715.19,4936.76 cw(c2728.47,4936.76) v1@2719.08,4946.15 ; v3(4996.3,4386.85) U8.J4@5015.98,4367.17 ; U8.J4@5008.48,4367.17 ccw(c4990.38,4367.17) 5003.18,4379.97 ccw(c5015.98,4392.77) U8.J4@5015.98,4374.67 ; U8.J4@5008.64,4367.17 ccw(c4990.92,4367.17) 5003.45,4379.7 ccw(c5015.98,4392.23) U8.J4@5015.98,4374.51 ; 5009.1,4374.05 cw(c5021.91,4386.85) 5003.8,4386.85 ccw(c5021.91,4386.85) 5009.1,4374.05 ; 5009.1,4374.05 ccw(c4996.3,4361.24) 4996.3,4379.35 cw(c4996.3,4361.24) 5009.1,4374.05
  MidLayer1 w4: v1@-687.48,3009.54 cw(c-687.48,2986.61) -671.26,3002.82 cw(c-655.04,3019.04) v1@-677.98,3019.04 ; v1@-687.48,3013.54 cw(c-687.48,3000.26) -678.09,3009.65 cw(c-668.7,3019.04) v1@-681.98,3019.04 ; v1(-687.48,3019.04) -668.48,3000.04 -599.7,3000.04 -513,3086.75 -513,3087 -507.5,3092.5 -507.5,3213.51 -352.74,3368.26 -324,3397.01 -324,3820 -277.23,3866.77 -277.23,4010.09 -279,4011.86 -279,4141.56 -150.56,4270 -89.85,4270 -60.92,4298.93 23.52,4383.37 23.52,4441.71 v1(194.86,4613.04) ; v1@185.36,4613.04 cw(c162.42,4613.04) 178.64,4596.82 cw(c194.86,4580.61) v1@194.86,4603.54 ; v1@189.36,4613.04 cw(c176.08,4613.04) 185.47,4603.65 cw(c194.86,4594.26) v1@194.86,4607.54 ; v1@1706.86,4582.21 cw(c1706.86,4559.27) 1723.07,4575.49 cw(c1739.29,4591.71) v1@1716.36,4591.71 ; v1@1706.86,4586.21 cw(c1706.86,4572.93) 1716.25,4582.32 cw(c1725.64,4591.71) v1@1712.36,4591.71 ; v1(1706.86,4591.71) 1756.86,4541.71 2353.29,4541.71 2376.12,4518.88 PROTOTYPE1.H22@2376.12,4208.23 ; PROTOTYPE1.H22@2355.62,4228.74 ccw(c2306.11,4278.25) 2376.12,4278.25 ccw(c2446.13,4278.25) PROTOTYPE1.H22@2396.63,4228.74 ; PROTOTYPE1.H22@2358.44,4225.91 ccw(c2315.77,4268.59) 2376.12,4268.59 ccw(c2436.48,4268.59) PROTOTYPE1.H22@2393.8,4225.91 ; PROTOTYPE1.H22@2361.27,4223.08 ccw(c2325.42,4258.93) 2376.12,4258.93 ccw(c2426.82,4258.93) PROTOTYPE1.H22@2390.97,4223.08 ; PROTOTYPE1.H22@2364.1,4220.26 ccw(c2335.08,4249.28) 2376.12,4249.28 ccw(c2417.16,4249.28) PROTOTYPE1.H22@2388.14,4220.26 ; PROTOTYPE1.H22@2366.93,4217.43 ccw(c2344.74,4239.62) 2376.12,4239.62 ccw(c2407.51,4239.62) PROTOTYPE1.H22@2385.31,4217.43 ; v1@4048.52,4957.21 cw(c4048.52,4934.27) 4064.74,4950.49 cw(c4080.96,4966.71) v1@4058.02,4966.71 ; v1@4048.52,4961.21 cw(c4048.52,4947.93) 4057.91,4957.32 cw(c4067.3,4966.71) v1@4054.02,4966.71 ; v1(4048.52,4966.71) 4069.53,4945.7 4128.17,4945.7 4157.69,4916.18 4157.69,4901.83 4250.98,4808.54 4253.11,4808.54 4315.19,4746.46 4315.19,4731.71 4290.19,4706.71 4290.19,4625.04 4298.52,4616.71 4405.9,4616.71 4532.5,4490.1 4532.5,4447.75 4571.54,4408.71 4769.94,4408.71 4791.8,4386.85 4860,4386.85 4870,4386.85 4918.62,4386.85 v3(4996.3,4386.85) ; v3@4991,4381.55 ccw(c4978.19,4368.74) 4978.19,4386.85 ccw(c4978.19,4404.96) v3@4991,4392.15 ; v3@4991.11,4381.66 ccw(c4978.57,4369.12) 4978.57,4386.85 ccw(c4978.57,4404.58) v3@4991.11,4392.04
  MidLayer2 w4: v1@194.86,4603.54 cw(c194.86,4580.61) 211.07,4596.82 cw(c227.29,4613.04) v1@204.36,4613.04 ; v1@194.86,4607.54 cw(c194.86,4594.26) 204.25,4603.65 cw(c213.64,4613.04) v1@200.36,4613.04 ; v1(194.86,4613.04) 233.86,4574.04 451.69,4574.04 505.46,4627.81 970.75,4627.81 1006.86,4591.71 v1(1706.86,4591.71) 1734.56,4564 2654,4564 2673.76,4583.76 UH2.7@2673.76,4713.23 ; v1@1700.14,4584.99 ccw(c1683.92,4568.77) 1683.92,4591.71 ccw(c1683.92,4614.64) v1@1700.14,4598.43 ; v1@1702.97,4587.82 ccw(c1693.58,4578.43) 1693.58,4591.71 ccw(c1693.58,4604.99) v1@1702.97,4595.6 ; v1@1706.86,4582.21 cw(c1706.86,4559.27) 1723.07,4575.49 cw(c1739.29,4591.71) v1@1716.36,4591.71 ; v1@1706.86,4586.21 cw(c1706.86,4572.93) 1716.25,4582.32 cw(c1725.64,4591.71) v1@1712.36,4591.71 ; UH2.7@2654.29,4693.77 cw(c2607.3,4646.78) 2673.76,4646.78 cw(c2740.22,4646.78) UH2.7@2693.22,4693.77 ; UH2.7@2657.12,4696.6 cw(c2616.96,4656.43) 2673.76,4656.43 cw(c2730.56,4656.43) UH2.7@2690.4,4696.6 ; UH2.7@2659.95,4699.43 cw(c2626.62,4666.09) 2673.76,4666.09 cw(c2720.9,4666.09) UH2.7@2687.57,4699.43 ; UH2.7@2662.78,4702.25 cw(c2636.27,4675.75) 2673.76,4675.75 cw(c2711.25,4675.75) UH2.7@2684.74,4702.25
  Bottom Layer w4: J33.B31@-766.3,3007.19 -699.33,3007.19 ; J33.B31@-706.23,3002.61 cw(c-699.33,2999.7) -699.33,3007.19 ; J33.B31@-706.23,3011.77 ccw(c-699.33,3014.69) -699.33,3007.19 ; v1(-687.48,3019.04) -699.33,3007.19 ; v1(2715.19,4950.04) 2732.69,4967.54 3805.67,4967.54 3814.67,4958.54 3874.85,4958.54 3898.31,4982 4033.23,4982 v1(4048.52,4966.71) ; v1@2715.19,4955.54 ccw(c2715.19,4968.82) 2724.58,4959.43 ccw(c2733.97,4950.04) v1@2720.69,4950.04 ; v1@2715.19,4959.54 ccw(c2715.19,4982.48) 2731.41,4966.26 ccw(c2747.63,4950.04) v1@2724.69,4950.04
ATE.UIO.IO24: J33.A32 PROTOTYPE1.H23 U8.G4 UH2.8 | length 9751
  Top Layer w4: J33.A32@-785.98,2967.82 -696.48,2967.82 ; J33.A32@-706.93,2961.84 cw(c-696.48,2955.69) -696.48,2967.82 ; J33.A32@-706.93,2973.8 ccw(c-696.48,2979.96) -696.48,2967.82 ; v1@-612.19,2947.66 ccw(c-628.41,2931.44) -628.41,2954.37 ccw(c-628.41,2977.31) v1@-612.19,2961.09 ; v1@-609.36,2950.49 ccw(c-618.75,2941.1) -618.75,2954.37 ccw(c-618.75,2967.65) v1@-609.36,2958.26 ; v1(-605.48,2954.37) -683.03,2954.37 -696.48,2967.82 ; PROTOTYPE1.H23@2476.12,4208.23 2631.86,4363.97 2631.86,4771.33 ; PROTOTYPE1.H23@2476.12,4221.23 ccw(c2476.12,4252.62) 2498.31,4230.43 ccw(c2520.51,4208.23) PROTOTYPE1.H23@2489.12,4208.23 ; PROTOTYPE1.H23@2476.12,4225.23 ccw(c2476.12,4266.28) 2505.14,4237.26 ccw(c2534.16,4208.23) PROTOTYPE1.H23@2493.12,4208.23 ; PROTOTYPE1.H23@2476.12,4229.23 ccw(c2476.12,4279.93) 2511.97,4244.08 ccw(c2547.82,4208.23) PROTOTYPE1.H23@2497.12,4208.23 ; PROTOTYPE1.H23@2476.12,4233.23 ccw(c2476.12,4293.59) 2518.8,4250.91 ccw(c2561.48,4208.23) PROTOTYPE1.H23@2501.12,4208.23 ; PROTOTYPE1.H23@2476.12,4237.23 ccw(c2476.12,4307.25) 2525.63,4257.74 ccw(c2575.13,4208.23) PROTOTYPE1.H23@2505.12,4208.23 ; UH2.8@2646.33,4810.91 cw(c2596.5,4806.7) 2631.86,4771.33 ; UH2.8@2650.31,4811.25 cw(c2607.72,4807.65) 2637.95,4777.42 cw(c2668.17,4747.2) UH2.8@2671.78,4789.79 ; UH2.8@2654.3,4811.59 cw(c2618.95,4808.6) 2644.04,4783.51 cw(c2669.12,4758.42) UH2.8@2672.11,4793.78 ; UH2.8@2658.29,4811.93 cw(c2630.18,4809.55) 2650.12,4789.6 cw(c2670.07,4769.65) UH2.8@2672.45,4797.76 ; UH2.8@2671.44,4785.8 ccw(c2667.22,4735.97) 2631.86,4771.33 ; UH2.8@2673.76,4813.23 2631.86,4771.33 ; v3(4996.3,4465.59) U8.G4@5015.98,4445.91 ; U8.G4@5008.48,4445.91 ccw(c4990.38,4445.91) 5003.18,4458.71 ccw(c5015.98,4471.51) U8.G4@5015.98,4453.41 ; U8.G4@5008.64,4445.91 ccw(c4990.92,4445.91) 5003.45,4458.44 ccw(c5015.98,4470.97) U8.G4@5015.98,4453.25 ; 5009.1,4452.79 cw(c5021.91,4465.59) 5003.8,4465.59 ccw(c5021.91,4465.59) 5009.1,4452.79 ; 5009.1,4452.79 ccw(c4996.3,4439.98) 4996.3,4458.09 cw(c4996.3,4439.98) 5009.1,4452.79
  MidLayer1 w4: v1(2406.86,2883.37) 2438.52,2915.04 2438.52,4170.64 ; v1@2406.86,2888.87 ccw(c2406.86,2902.15) 2416.25,2892.76 ccw(c2425.64,2883.37) v1@2412.36,2883.37 ; v1@2406.86,2892.87 ccw(c2406.86,2915.81) 2423.07,2899.59 ccw(c2439.29,2883.37) v1@2416.36,2883.37 ; PROTOTYPE1.H23@2447.78,4202.1 cw(c2414.32,4194.85) 2438.53,4170.64 ; PROTOTYPE1.H23@2451.69,4202.94 cw(c2422.84,4196.7) 2443.71,4175.83 cw(c2464.58,4154.95) PROTOTYPE1.H23@2470.83,4183.8 ; PROTOTYPE1.H23@2455.6,4203.79 cw(c2431.37,4198.54) 2448.9,4181.01 cw(c2466.43,4163.48) PROTOTYPE1.H23@2471.68,4187.71 ; PROTOTYPE1.H23@2459.51,4204.64 cw(c2439.89,4200.39) 2454.08,4186.2 cw(c2468.27,4172) PROTOTYPE1.H23@2472.52,4191.62 ; PROTOTYPE1.H23@2469.98,4179.89 ccw(c2462.74,4146.43) 2438.53,4170.64 ; PROTOTYPE1.H23@2476.12,4208.23 2438.52,4170.64 ; v1(4615.19,4598.37) 4652.56,4598.37 4683.9,4567.04 4707.88,4567.04 4748.52,4526.39 4748.52,4475 4758.15,4465.37 4855.04,4465.37 4855.26,4465.59 4860,4465.59 4870,4465.59 4918.62,4465.59 v3(4996.3,4465.59) ; v1@4619.08,4594.49 cw(c4628.47,4585.1) 4628.47,4598.37 cw(c4628.47,4611.65) v1@4619.08,4602.26 ; v1@4621.91,4591.66 cw(c4638.13,4575.44) 4638.13,4598.37 cw(c4638.13,4621.31) v1@4621.91,4605.09 ; v3@4991.11,4460.4 ccw(c4978.57,4447.86) 4978.57,4465.59 ccw(c4978.57,4483.32) v3@4991.11,4470.78 ; 4978.19,4465.59 cw(c4978.19,4447.48) 4991,4460.29 ccw(c4978.19,4447.48) 4978.19,4465.59 ; 4978.19,4465.59 ccw(c4978.19,4483.7) 4991,4470.89 cw(c4978.19,4483.7) 4978.19,4465.59
  MidLayer2 w4: v1(-605.48,2954.37) -501.48,3058.37 186.63,3058.37 359,2886 2206.5,2886 2212.21,2891.71 2293.17,2891.71 2301.5,2883.37 v1(2406.86,2883.37) ; v1@-605.48,2959.87 ccw(c-605.48,2973.15) -596.09,2963.76 ccw(c-586.7,2954.37) v1@-599.98,2954.37 ; v1@-605.48,2963.87 ccw(c-605.48,2986.81) -589.26,2970.59 ccw(c-573.04,2954.37) v1@-595.98,2954.37 ; v1@2400.14,2876.66 ccw(c2383.92,2860.44) 2383.92,2883.37 ccw(c2383.92,2906.31) v1@2400.14,2890.09 ; v1@2402.97,2879.49 ccw(c2393.58,2870.1) 2393.58,2883.37 ccw(c2393.58,2896.65) v1@2402.97,2887.26
  Bottom Layer w4: UH2.8@2673.76,4813.23 2720.28,4766.71 ; UH2.8@2673.9,4793.71 cw(c2674.22,4747.7) 2706.76,4780.23 cw(c2739.3,4812.77) UH2.8@2693.29,4813.09 ; UH2.8@2673.87,4797.71 cw(c2674.13,4761.12) 2700,4786.99 cw(c2725.87,4812.86) UH2.8@2689.29,4813.12 ; UH2.8@2673.93,4789.71 cw(c2674.32,4734.27) 2713.52,4773.47 cw(c2752.72,4812.67) UH2.8@2697.29,4813.07 ; UH2.8@2673.95,4785.71 cw(c2674.42,4720.85) 2720.28,4766.71 ; UH2.8@2701.29,4813.04 ccw(c2766.15,4812.58) 2720.28,4766.71 ; 3316.37,4766.37 3316.71,4766.71 ; v1(4615.19,4598.37) 4631.86,4598.37 ; v1@4623.36,4593.53 cw(c4631.86,4588.51) 4631.86,4598.37 ; v1@4623.36,4603.22 ccw(c4631.86,4608.24) 4631.86,4598.37 ; 2720.28,4766.71 3316.71,4766.71 ; 3316.71,4766.71 3325.71,4775.71 4594.88,4775.71 4640.19,4730.39 4640.19,4606.71 4631.86,4598.37
ATE.UIO.IO25: J33.B32 PROTOTYPE1.H24 U8.J5 UH2.9 | length 10009.2
  Top Layer w4: v1(2598.52,4382.04) 2623.52,4407.04 2623.52,4988.73 2635.17,5000.37 2804.63,5000.37 2823.52,4981.48 2823.52,4763 UH2.9@2773.76,4713.23 ; v1@2598.52,4387.54 ccw(c2598.52,4400.82) 2607.91,4391.43 ccw(c2617.3,4382.04) v1@2604.02,4382.04 ; v1@2598.52,4391.54 ccw(c2598.52,4414.48) 2614.74,4398.26 ccw(c2630.96,4382.04) v1@2608.02,4382.04 ; UH2.9@2773.76,4728.76 ccw(c2773.76,4766.25) 2800.27,4739.74 ccw(c2826.77,4713.23) UH2.9@2789.29,4713.23 ; UH2.9@2773.76,4732.76 ccw(c2773.76,4779.91) 2807.1,4746.57 ccw(c2840.43,4713.23) UH2.9@2793.29,4713.23 ; UH2.9@2773.76,4736.76 ccw(c2773.76,4793.56) 2813.92,4753.4 ccw(c2854.08,4713.23) UH2.9@2797.29,4713.23 ; UH2.9@2773.76,4740.76 ccw(c2773.76,4807.22) 2820.75,4760.23 ccw(c2867.74,4713.23) UH2.9@2801.29,4713.23 ; v3(5035.67,4386.85) U8.J5@5055.35,4367.17 ; U8.J5@5047.85,4367.17 ccw(c5029.75,4367.17) 5042.55,4379.97 ccw(c5055.35,4392.77) U8.J5@5055.35,4374.67 ; U8.J5@5048.01,4367.17 ccw(c5030.29,4367.17) 5042.82,4379.7 ccw(c5055.35,4392.23) U8.J5@5055.35,4374.51 ; 5048.47,4374.05 ccw(c5035.67,4361.24) 5035.67,4379.35 cw(c5035.67,4361.24) 5048.47,4374.05 ; 5048.47,4374.05 cw(c5061.28,4386.85) 5043.17,4386.85 ccw(c5061.28,4386.85) 5048.47,4374.05
  MidLayer1 w4: v1(990.19,3208.37) 1123.52,3341.71 1123.52,4058.37 1131.86,4066.71 1501.71,4066.71 1520,4085 1520,4359.56 v1(1497.52,4382.04) ; v1@990.19,3213.87 ccw(c990.19,3227.15) 999.58,3217.76 ccw(c1008.97,3208.37) v1@995.69,3208.37 ; v1@990.19,3217.87 ccw(c990.19,3240.81) 1006.41,3224.59 ccw(c1022.63,3208.37) v1@999.69,3208.37 ; v1@1497.52,4372.54 cw(c1497.52,4349.61) 1513.74,4365.82 cw(c1529.96,4382.04) v1@1507.02,4382.04 ; v1@1497.52,4376.54 cw(c1497.52,4363.26) 1506.91,4372.65 cw(c1516.3,4382.04) v1@1503.02,4382.04 ; PROTOTYPE1.H24@2555.62,4228.74 ccw(c2506.11,4278.25) 2576.12,4278.25 ccw(c2646.13,4278.25) PROTOTYPE1.H24@2596.63,4228.74 ; PROTOTYPE1.H24@2558.44,4225.91 ccw(c2515.77,4268.59) 2576.12,4268.59 ccw(c2636.48,4268.59) PROTOTYPE1.H24@2593.8,4225.91 ; PROTOTYPE1.H24@2561.27,4223.08 ccw(c2525.42,4258.93) 2576.12,4258.93 ccw(c2626.82,4258.93) PROTOTYPE1.H24@2590.97,4223.08 ; PROTOTYPE1.H24@2564.1,4220.26 ccw(c2535.08,4249.28) 2576.12,4249.28 ccw(c2617.16,4249.28) PROTOTYPE1.H24@2588.14,4220.26 ; PROTOTYPE1.H24@2566.93,4217.43 ccw(c2544.74,4239.62) 2576.12,4239.62 ccw(c2607.51,4239.62) PROTOTYPE1.H24@2585.31,4217.43 ; PROTOTYPE1.H24@2576.12,4208.23 2576.12,4359.64 v1(2598.52,4382.04) ; v1@2589.02,4382.04 cw(c2566.09,4382.04) 2582.31,4365.82 cw(c2598.52,4349.61) v1@2598.52,4372.54 ; v1@2593.02,4382.04 cw(c2579.75,4382.04) 2589.14,4372.65 cw(c2598.52,4363.26) v1@2598.52,4376.54 ; v1(4310,4640) 4393.92,4640 4617.21,4416.71 4773.26,4416.71 4787.6,4402.36 4805,4402.36 4918.62,4402.36 5012.16,4402.36 cw(c5012.16,4388.31) 5022.09,4398.24 ; v1@4313.89,4636.11 cw(c4323.28,4626.72) 4323.28,4640 cw(c4323.28,4653.28) v1@4313.89,4643.89 ; v1@4316.72,4633.28 cw(c4332.93,4617.06) 4332.93,4640 cw(c4332.93,4662.93) v1@4316.72,4646.72 ; v3@5028.2,4386.2 ccw(c5010.16,4384.62) 5021.8,4398.49 ccw(c5033.44,4412.36) v3@5035.02,4394.32
  Bottom Layer w4: J33.B32@-785.98,2967.82 -697.82,2967.82 ; J33.B32@-706.6,2962.45 cw(c-697.82,2957.96) -697.82,2967.82 ; J33.B32@-706.6,2973.19 ccw(c-697.82,2977.68) -697.82,2967.82 ; v1@980.69,3208.37 ccw(c957.76,3208.37) 973.97,3224.59 ccw(c990.19,3240.81) v1@990.19,3217.87 ; v1@984.69,3208.37 ccw(c971.41,3208.37) 980.8,3217.76 ccw(c990.19,3227.15) v1@990.19,3213.87 ; v1(990.19,3208.37) 964.86,3233.71 786.29,3233.71 736.78,3184.19 -15.69,3184.19 -26.5,3195 -550,3195 -562.41,3182.59 -562.41,2947.59 -575,2935 -620,2935 -640,2955 -685,2955 -697.82,2967.82 ; v1(1497.52,4382.04) 1513.19,4366.37 2568,4366.37 2583.67,4382.04 v1(2598.52,4382.04) ; UH2.9@2773.76,4713.23 2810.52,4750 2885,4750 2898.52,4750.04 2931.86,4716.71 2931.86,4633.14 2940.29,4624.71 4294.71,4624.71 v1(4310,4640) ; UH2.9@2777.42,4732.42 ccw(c2782.11,4757.04) 2799.84,4739.31 ccw(c2817.56,4721.59) UH2.9@2792.94,4716.89 ; UH2.9@2778.17,4736.35 ccw(c2783.82,4766.01) 2805.18,4744.66 ccw(c2826.54,4723.3) UH2.9@2796.87,4717.64 ; UH2.9@2778.92,4740.27 ccw(c2785.54,4774.99) 2810.52,4750 ccw(c2835.51,4725.01) UH2.9@2800.8,4718.39
ATE.UIO.IO26: J33.A33 PROTOTYPE1.H25 U8.P7 UH2.10 | length 10166.3
  Top Layer w4: J33.A33@-785.98,2928.45 -696.55,2928.45 ; J33.A33@-706.91,2922.51 cw(c-696.55,2916.45) -696.55,2928.45 ; J33.A33@-706.92,2934.4 ccw(c-696.55,2940.45) -696.55,2928.45 ; v1(-684.81,2916.71) -696.55,2928.45 ; PROTOTYPE1.H25@2676.12,4208.23 2715.19,4247.3 ; PROTOTYPE1.H25@2679.19,4224.96 ccw(c2683.22,4246.94) 2699.02,4231.14 ccw(c2714.83,4215.33) PROTOTYPE1.H25@2692.84,4211.3 ; PROTOTYPE1.H25@2679.91,4228.89 ccw(c2684.89,4256.05) 2704.41,4236.52 ccw(c2723.94,4217) PROTOTYPE1.H25@2696.78,4212.02 ; PROTOTYPE1.H25@2680.63,4232.82 ccw(c2686.56,4265.16) 2709.8,4241.91 ccw(c2733.04,4218.67) PROTOTYPE1.H25@2700.71,4212.74 ; PROTOTYPE1.H25@2681.35,4236.76 ccw(c2688.23,4274.26) 2715.19,4247.3 ; PROTOTYPE1.H25@2704.65,4213.46 cw(c2742.15,4220.34) 2715.19,4247.3 ; UH2.10@2746.23,4813.23 cw(c2679.77,4813.23) 2726.77,4766.24 cw(c2773.76,4719.25) UH2.10@2773.76,4785.71 ; UH2.10@2750.23,4813.23 cw(c2693.43,4813.23) 2733.59,4773.07 cw(c2773.76,4732.91) UH2.10@2773.76,4789.71 ; UH2.10@2754.23,4813.23 cw(c2707.09,4813.23) 2740.42,4779.9 cw(c2773.76,4746.57) UH2.10@2773.76,4793.71 ; UH2.10@2758.23,4813.23 cw(c2720.74,4813.23) 2747.25,4786.73 cw(c2773.76,4760.22) UH2.10@2773.76,4797.71 ; UH2.10@2773.76,4813.23 2715.19,4754.66 2715.19,4247.3 ; v3(5114.41,4150.63) U8.P7@5134.09,4170.31 ; U8.P7@5126.59,4170.31 cw(c5108.49,4170.31) 5121.29,4157.51 cw(c5134.09,4144.71) U8.P7@5134.09,4162.81 ; U8.P7@5126.75,4170.31 cw(c5109.03,4170.31) 5121.56,4157.78 cw(c5134.09,4145.25) U8.P7@5134.09,4162.97 ; 5127.21,4163.43 cw(c5114.41,4176.24) 5114.41,4158.13 ccw(c5114.41,4176.24) 5127.21,4163.43 ; 5127.21,4163.43 ccw(c5140.02,4150.63) 5121.91,4150.63 cw(c5140.02,4150.63) 5127.21,4163.43
  MidLayer1 w4: v1(1841.52,3216.71) 2246.71,3216.71 2415.19,3385.19 2415.19,4390.19 2445,4420 2660,4420 2676.12,4403.88 PROTOTYPE1.H25@2676.12,4208.23 ; v1@1845.41,3212.82 cw(c1854.8,3203.43) 1854.8,3216.71 cw(c1854.8,3229.99) v1@1845.41,3220.6 ; v1@1848.24,3209.99 cw(c1864.46,3193.77) 1864.46,3216.71 cw(c1864.46,3239.64) v1@1848.24,3223.43 ; PROTOTYPE1.H25@2655.62,4228.74 ccw(c2606.11,4278.25) 2676.12,4278.25 ccw(c2746.13,4278.25) PROTOTYPE1.H25@2696.63,4228.74 ; PROTOTYPE1.H25@2658.44,4225.91 ccw(c2615.77,4268.59) 2676.12,4268.59 ccw(c2736.48,4268.59) PROTOTYPE1.H25@2693.8,4225.91 ; PROTOTYPE1.H25@2661.27,4223.08 ccw(c2625.42,4258.93) 2676.12,4258.93 ccw(c2726.82,4258.93) PROTOTYPE1.H25@2690.97,4223.08 ; PROTOTYPE1.H25@2664.1,4220.26 ccw(c2635.08,4249.28) 2676.12,4249.28 ccw(c2717.16,4249.28) PROTOTYPE1.H25@2688.14,4220.26 ; PROTOTYPE1.H25@2666.93,4217.43 ccw(c2644.74,4239.62) 2676.12,4239.62 ccw(c2707.51,4239.62) PROTOTYPE1.H25@2685.31,4217.43
  MidLayer2 w4: v1(-684.81,2916.71) -526.48,3075.04 192.59,3075.04 365.63,2902 1020.13,2902 1318.17,3200.04 1656.73,3200.04 1681.69,3225 1725,3225 1749.96,3200.04 1790.04,3200.04 1806.71,3216.71 v1(1841.52,3216.71) ; v1@-684.81,2922.21 ccw(c-684.81,2935.49) -675.42,2926.1 ccw(c-666.03,2916.71) v1@-679.31,2916.71 ; v1@-684.81,2926.21 ccw(c-684.81,2949.14) -668.59,2932.93 ccw(c-652.37,2916.71) v1@-675.31,2916.71 ; v1@1834.81,3209.99 ccw(c1818.59,3193.77) 1818.59,3216.71 ccw(c1818.59,3239.64) v1@1834.81,3223.43 ; v1@1837.64,3212.82 ccw(c1828.25,3203.43) 1828.25,3216.71 ccw(c1828.25,3229.99) v1@1837.64,3220.6 ; PROTOTYPE1.H25@2655.62,4228.74 ccw(c2606.11,4278.25) 2676.12,4278.25 ccw(c2746.13,4278.25) PROTOTYPE1.H25@2696.63,4228.74 ; PROTOTYPE1.H25@2658.44,4225.91 ccw(c2615.77,4268.59) 2676.12,4268.59 ccw(c2736.48,4268.59) PROTOTYPE1.H25@2693.8,4225.91 ; PROTOTYPE1.H25@2661.27,4223.08 ccw(c2625.42,4258.93) 2676.12,4258.93 ccw(c2726.82,4258.93) PROTOTYPE1.H25@2690.97,4223.08 ; PROTOTYPE1.H25@2664.1,4220.26 ccw(c2635.08,4249.28) 2676.12,4249.28 ccw(c2717.16,4249.28) PROTOTYPE1.H25@2688.14,4220.26 ; PROTOTYPE1.H25@2666.93,4217.43 ccw(c2644.74,4239.62) 2676.12,4239.62 ccw(c2707.51,4239.62) PROTOTYPE1.H25@2685.31,4217.43 ; PROTOTYPE1.H25@2676.12,4208.23 2676.12,4351.12 2708.71,4383.71 4074.67,4383.71 4175,4283.37 4290.19,4283.37 4306.86,4300.04 4406.86,4300.04 4581.86,4125.04 4598.52,4125.04 4640.19,4166.71 4670.19,4166.71 4695.19,4141.71 4715.19,4141.71 4740.19,4166.71 4765,4166.71 4796.59,4135.12 4855.26,4135.12 4860,4135.12 4870,4135.12 4997.36,4135.12 5090.9,4135.12 ccw(c5090.9,4149.17) 5100.83,4139.24 ; v3@5106.94,4151.28 cw(c5088.9,4152.86) 5100.54,4138.99 cw(c5112.18,4125.12) v3@5113.76,4143.16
